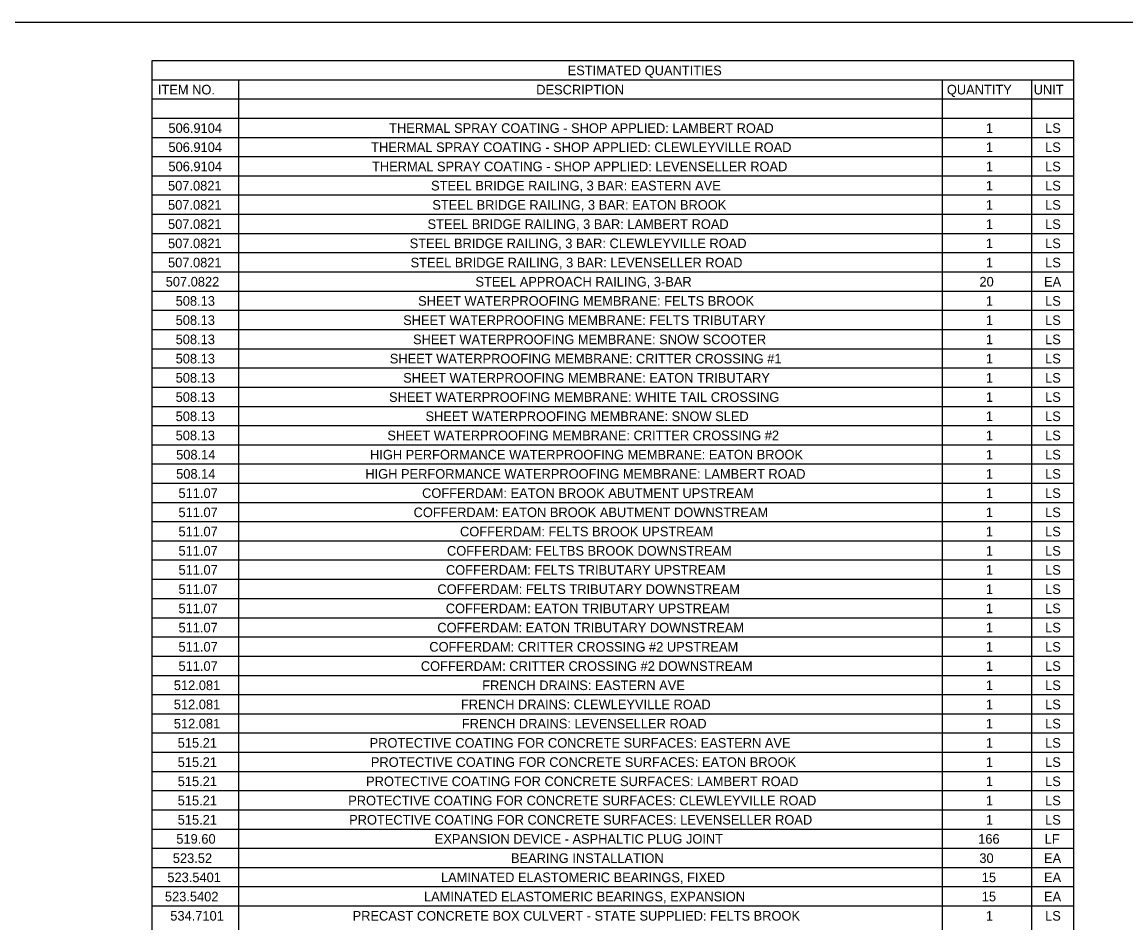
# Model space of a CAD drawing. Extents: x -18.7 to 5.6, y -2.7 to 4.
# Drawn here: x -16.637 to -15.505, y 3.091 to 4.014 of the extents above; entities that cross this region are included whole.
import ezdxf

# ---------------------------------------------------------------- set-up
doc = ezdxf.new("R2010")
doc.units = 0
doc.layers.add('ANNOTATION', color=7, linetype='Continuous')
doc.layers.add('BORDER', color=7, linetype='Continuous')

msp = doc.modelspace()

# ---------------------------------------------------------------- linework, layer by layer
at = {"layer": 'ANNOTATION'}
msp.add_lwpolyline([(-17.663, 4.0141), (-13.3075, 4.0141), (-13.3075, 2.1719), (-17.663, 2.1719)], close=True, dxfattribs=at)
at = {"layer": 'BORDER'}
for p, q in [((-16.5036, 3.9551), (-15.5593, 3.9551)), ((-16.415, 3.9551), (-16.415, 2.2424)), ((-15.6937, 3.9551), (-15.6937, 2.2424)), ((-15.6023, 3.9551), (-15.6023, 2.2424)), ((-16.5036, 3.9354), (-15.5593, 3.9354)), ((-16.5036, 3.9157), (-15.5593, 3.9157)), ((-16.5036, 3.896), (-15.5593, 3.896)), ((-16.5036, 3.8764), (-15.5593, 3.8764)), ((-16.5036, 3.8567), (-15.5593, 3.8567)), ((-16.5036, 3.837), (-15.5593, 3.837)), ((-16.5036, 3.8173), (-15.5593, 3.8173)), ((-16.5036, 3.7976), (-15.5593, 3.7976)), ((-16.5036, 3.7779), (-15.5593, 3.7779)), ((-16.5036, 3.7582), (-15.5593, 3.7582)), ((-16.5036, 3.7386), (-15.5593, 3.7386)), ((-16.5036, 3.7189), (-15.5593, 3.7189)), ((-16.5036, 3.6992), (-15.5593, 3.6992)), ((-16.5036, 3.6795), (-15.5593, 3.6795)), ((-16.5036, 3.6598), (-15.5593, 3.6598)), ((-16.5036, 3.6401), (-15.5593, 3.6401)), ((-16.5036, 3.6204), (-15.5593, 3.6204)), ((-16.5036, 3.6008), (-15.5593, 3.6008)), ((-16.5036, 3.5811), (-15.5593, 3.5811)), ((-16.5036, 3.5614), (-15.5593, 3.5614)), ((-16.5036, 3.5417), (-15.5593, 3.5417)), ((-16.5036, 3.522), (-15.5593, 3.522)), ((-16.5036, 3.5023), (-15.5593, 3.5023)), ((-16.5036, 3.4826), (-15.5593, 3.4826)), ((-16.5036, 3.463), (-15.5593, 3.463)), ((-16.5036, 3.4433), (-15.5593, 3.4433)), ((-16.5036, 3.4236), (-15.5593, 3.4236)), ((-16.5036, 3.4039), (-15.5593, 3.4039)), ((-16.5036, 3.3842), (-15.5593, 3.3842)), ((-16.5036, 3.3645), (-15.5593, 3.3645)), ((-16.5036, 3.3448), (-15.5593, 3.3448)), ((-16.5036, 3.3251), (-15.5593, 3.3251)), ((-16.5036, 3.3055), (-15.5593, 3.3055)), ((-16.5036, 3.2858), (-15.5593, 3.2858)), ((-16.5036, 3.2661), (-15.5593, 3.2661)), ((-16.5036, 3.2464), (-15.5593, 3.2464)), ((-16.5036, 3.2267), (-15.5593, 3.2267)), ((-16.5036, 3.207), (-15.5593, 3.207)), ((-16.5036, 3.1873), (-15.5593, 3.1873)), ((-16.5036, 3.1677), (-15.5593, 3.1677)), ((-16.5036, 3.148), (-15.5593, 3.148)), ((-16.5036, 3.1283), (-15.5593, 3.1283)), ((-16.5036, 3.1086), (-15.5593, 3.1086))]:
    msp.add_line(p, q, dxfattribs=at)
msp.add_lwpolyline([(-16.5036, 3.9748), (-15.5593, 3.9748), (-15.5593, 2.2424), (-16.5036, 2.2424)], close=True, dxfattribs=at)

# ---------------------------------------------------------------- texts
at = {"layer": 'ANNOTATION'}
for s, height, p in [('506.9104', 0.00984, (-16.4869, 3.9006)), ('THERMAL SPRAY COATING - SHOP APPLIED: LAMBERT ROAD', 0.009843, (-16.2607, 3.9006)), ('1', 0.00984, (-15.649, 3.9006)), ('LS', 0.00984, (-15.5883, 3.9006)), ('506.9104', 0.00984, (-16.4869, 3.881)), ('THERMAL SPRAY COATING - SHOP APPLIED: CLEWLEYVILLE ROAD', 0.009843, (-16.2791, 3.881)), ('1', 0.00984, (-15.649, 3.881)), ('LS', 0.00984, (-15.5883, 3.881)), ('506.9104', 0.00984, (-16.4869, 3.8613)), ('THERMAL SPRAY COATING - SHOP APPLIED: LEVENSELLER ROAD', 0.009843, (-16.2782, 3.8613)), ('1', 0.00984, (-15.649, 3.8613)), ('LS', 0.00984, (-15.5883, 3.8613)), ('507.0821', 0.00984, (-16.4873, 3.8416)), ('STEEL BRIDGE RAILING, 3 BAR: EASTERN AVE', 0.009843, (-16.2177, 3.8416)), ('1', 0.00984, (-15.649, 3.8416)), ('LS', 0.00984, (-15.5883, 3.8416)), ('507.0821', 0.00984, (-16.4873, 3.8219)), ('STEEL BRIDGE RAILING, 3 BAR: EATON BROOK', 0.009843, (-16.2164, 3.8219)), ('1', 0.00984, (-15.649, 3.8219)), ('LS', 0.00984, (-15.5883, 3.8219)), ('507.0821', 0.00984, (-16.4873, 3.8022)), ('STEEL BRIDGE RAILING, 3 BAR: LAMBERT ROAD', 0.009843, (-16.2213, 3.8022)), ('1', 0.00984, (-15.649, 3.8022)), ('LS', 0.00984, (-15.5883, 3.8022)), ('507.0821', 0.00984, (-16.4873, 3.7825)), ('STEEL BRIDGE RAILING, 3 BAR: CLEWLEYVILLE ROAD', 0.009843, (-16.2396, 3.7825)), ('1', 0.00984, (-15.649, 3.7825)), ('LS', 0.00984, (-15.5883, 3.7825)), ('507.0821', 0.00984, (-16.4873, 3.7628)), ('STEEL BRIDGE RAILING, 3 BAR: LEVENSELLER ROAD', 0.009843, (-16.2387, 3.7628)), ('1', 0.00984, (-15.649, 3.7628)), ('LS', 0.00984, (-15.5883, 3.7628)), ('507.0822', 0.00984, (-16.4897, 3.7432)), ('STEEL APPROACH RAILING, 3-BAR', 0.009843, (-16.1722, 3.7432)), ('20', 0.00984, (-15.6556, 3.7432)), ('EA', 0.00984, (-15.5894, 3.7432)), ('508.13', 0.00984, (-16.4795, 3.7235)), ('SHEET WATERPROOFING MEMBRANE: FELTS BROOK', 0.009843, (-16.231, 3.7235)), ('1', 0.00984, (-15.649, 3.7235)), ('LS', 0.00984, (-15.5883, 3.7235)), ('508.13', 0.00984, (-16.4795, 3.7038)), ('SHEET WATERPROOFING MEMBRANE: FELTS TRIBUTARY', 0.009843, (-16.2463, 3.7038)), ('1', 0.00984, (-15.649, 3.7038)), ('LS', 0.00984, (-15.5883, 3.7038)), ('508.13', 0.00984, (-16.4795, 3.6841)), ('SHEET WATERPROOFING MEMBRANE: SNOW SCOOTER', 0.009843, (-16.2362, 3.6841)), ('1', 0.00984, (-15.649, 3.6841)), ('LS', 0.00984, (-15.5883, 3.6841)), ('508.13', 0.00984, (-16.4795, 3.6644)), ('SHEET WATERPROOFING MEMBRANE: CRITTER CROSSING #1', 0.009843, (-16.26, 3.6644)), ('1', 0.00984, (-15.649, 3.6644)), ('LS', 0.00984, (-15.5883, 3.6644)), ('508.13', 0.00984, (-16.4795, 3.6447)), ('SHEET WATERPROOFING MEMBRANE: EATON TRIBUTARY', 0.009843, (-16.2463, 3.6447)), ('LS', 0.00984, (-15.5883, 3.6447)), ('1', 0.00984, (-15.649, 3.6447)), ('508.13', 0.00984, (-16.4795, 3.625)), ('SHEET WATERPROOFING MEMBRANE: WHITE TAIL CROSSING', 0.009843, (-16.2608, 3.625)), ('1', 0.00984, (-15.649, 3.625)), ('LS', 0.00984, (-15.5883, 3.625)), ('508.13', 0.00984, (-16.4795, 3.6053)), ('SHEET WATERPROOFING MEMBRANE: SNOW SLED', 0.009843, (-16.2234, 3.6053)), ('1', 0.00984, (-15.649, 3.6053)), ('LS', 0.00984, (-15.5883, 3.6053)), ('508.13', 0.00984, (-16.4795, 3.5857)), ('SHEET WATERPROOFING MEMBRANE: CRITTER CROSSING #2', 0.009843, (-16.2625, 3.5857)), ('1', 0.00984, (-15.649, 3.5857)), ('LS', 0.00984, (-15.5883, 3.5857)), ('508.14', 0.00984, (-16.479, 3.566)), ('HIGH PERFORMANCE WATERPROOFING MEMBRANE: EATON BROOK', 0.009843, (-16.2803, 3.566)), ('1', 0.00984, (-15.649, 3.566)), ('LS', 0.00984, (-15.5883, 3.566)), ('508.14', 0.00984, (-16.479, 3.5463)), ('HIGH PERFORMANCE WATERPROOFING MEMBRANE: LAMBERT ROAD', 0.009843, (-16.2851, 3.5463)), ('1', 0.00984, (-15.649, 3.5463)), ('LS', 0.00984, (-15.5883, 3.5463)), ('511.07', 0.00984, (-16.4766, 3.5266)), ('COFFERDAM: EATON BROOK ABUTMENT UPSTREAM', 0.009843, (-16.2269, 3.5266)), ('1', 0.00984, (-15.649, 3.5266)), ('LS', 0.00984, (-15.5883, 3.5266)), ('511.07', 0.00984, (-16.4766, 3.5069)), ('COFFERDAM: EATON BROOK ABUTMENT DOWNSTREAM', 0.009843, (-16.2356, 3.5069)), ('1', 0.00984, (-15.649, 3.5069)), ('LS', 0.00984, (-15.5883, 3.5069)), ('511.07', 0.00984, (-16.4766, 3.4872)), ('COFFERDAM: FELTS BROOK UPSTREAM', 0.009843, (-16.188, 3.4872)), ('1', 0.00984, (-15.649, 3.4872)), ('LS', 0.00984, (-15.5883, 3.4872)), ('511.07', 0.00984, (-16.4766, 3.4675)), ('COFFERDAM: FELTBS BROOK DOWNSTREAM', 0.009843, (-16.2014, 3.4675)), ('1', 0.00984, (-15.649, 3.4675)), ('LS', 0.00984, (-15.5883, 3.4675)), ('511.07', 0.00984, (-16.4766, 3.4479)), ('COFFERDAM: FELTS TRIBUTARY UPSTREAM', 0.009843, (-16.2025, 3.4479)), ('1', 0.00984, (-15.649, 3.4479)), ('LS', 0.00984, (-15.5883, 3.4479)), ('511.07', 0.00984, (-16.4766, 3.4282)), ('COFFERDAM: FELTS TRIBUTARY DOWNSTREAM', 0.009843, (-16.2112, 3.4282)), ('1', 0.00984, (-15.649, 3.4282)), ('LS', 0.00984, (-15.5883, 3.4282)), ('511.07', 0.00984, (-16.4766, 3.4085)), ('COFFERDAM: EATON TRIBUTARY UPSTREAM', 0.009843, (-16.2026, 3.4085)), ('1', 0.00984, (-15.649, 3.4085)), ('LS', 0.00984, (-15.5883, 3.4085)), ('511.07', 0.00984, (-16.4766, 3.3888)), ('COFFERDAM: EATON TRIBUTARY DOWNSTREAM', 0.009843, (-16.2113, 3.3888)), ('1', 0.00984, (-15.649, 3.3888)), ('LS', 0.00984, (-15.5883, 3.3888)), ('511.07', 0.00984, (-16.4766, 3.3691)), ('COFFERDAM: CRITTER CROSSING #2 UPSTREAM', 0.009843, (-16.2195, 3.3691)), ('1', 0.00984, (-15.649, 3.3691)), ('LS', 0.00984, (-15.5883, 3.3691)), ('511.07', 0.00984, (-16.4766, 3.3494)), ('COFFERDAM: CRITTER CROSSING #2 DOWNSTREAM', 0.009843, (-16.2282, 3.3494)), ('1', 0.00984, (-15.649, 3.3494)), ('LS', 0.00984, (-15.5883, 3.3494)), ('512.081', 0.00984, (-16.4814, 3.3297)), ('FRENCH DRAINS: EASTERN AVE', 0.009843, (-16.1653, 3.3297)), ('1', 0.00984, (-15.649, 3.3297)), ('LS', 0.00984, (-15.5883, 3.3297)), ('512.081', 0.00984, (-16.4814, 3.3101)), ('FRENCH DRAINS: CLEWLEYVILLE ROAD', 0.009843, (-16.1871, 3.3101)), ('1', 0.00984, (-15.649, 3.3101)), ('LS', 0.00984, (-15.5883, 3.3101)), ('512.081', 0.00984, (-16.4814, 3.2904)), ('FRENCH DRAINS: LEVENSELLER ROAD', 0.009843, (-16.1862, 3.2904)), ('1', 0.00984, (-15.649, 3.2904)), ('LS', 0.00984, (-15.5883, 3.2904)), ('515.21', 0.00984, (-16.4774, 3.2707)), ('PROTECTIVE COATING FOR CONCRETE SURFACES: EASTERN AVE', 0.009843, (-16.2807, 3.2707)), ('1', 0.00984, (-15.649, 3.2707)), ('LS', 0.00984, (-15.5883, 3.2707)), ('515.21', 0.00984, (-16.4774, 3.251)), ('PROTECTIVE COATING FOR CONCRETE SURFACES: EATON BROOK', 0.009843, (-16.2794, 3.251)), ('1', 0.00984, (-15.649, 3.251)), ('LS', 0.00984, (-15.5883, 3.251)), ('515.21', 0.00984, (-16.4774, 3.2313)), ('PROTECTIVE COATING FOR CONCRETE SURFACES: LAMBERT ROAD', 0.009843, (-16.2843, 3.2313)), ('1', 0.00984, (-15.649, 3.2313)), ('LS', 0.00984, (-15.5883, 3.2313)), ('515.21', 0.00984, (-16.4774, 3.2116)), ('PROTECTIVE COATING FOR CONCRETE SURFACES: CLEWLEYVILLE ROAD', 0.009843, (-16.3026, 3.2116)), ('1', 0.00984, (-15.649, 3.2116)), ('LS', 0.00984, (-15.5883, 3.2116)), ('515.21', 0.00984, (-16.4774, 3.1919)), ('PROTECTIVE COATING FOR CONCRETE SURFACES: LEVENSELLER ROAD', 0.009843, (-16.3017, 3.1919)), ('1', 0.00984, (-15.649, 3.1919)), ('LS', 0.00984, (-15.5883, 3.1919)), ('519.60', 0.00984, (-16.4788, 3.1723)), ('EXPANSION DEVICE - ASPHALTIC PLUG JOINT', 0.009843, (-16.2139, 3.1723)), ('166', 0.00984, (-15.6569, 3.1723)), ('LF', 0.00984, (-15.5887, 3.1723)), ('523.52', 0.00984, (-16.4824, 3.1526)), ('BEARING INSTALLATION', 0.009843, (-16.1358, 3.1526)), ('30', 0.00984, (-15.6557, 3.1526)), ('EA', 0.00984, (-15.5894, 3.1526)), ('523.5401', 0.00984, (-16.488, 3.1329)), ('LAMINATED ELASTOMERIC BEARINGS, FIXED', 0.009843, (-16.2076, 3.1329)), ('15', 0.00984, (-15.6532, 3.1329)), ('EA', 0.00984, (-15.5894, 3.1329)), ('523.5402', 0.00984, (-16.4905, 3.1132)), ('LAMINATED ELASTOMERIC BEARINGS, EXPANSION', 0.009843, (-16.225, 3.1132)), ('15', 0.00984, (-15.6532, 3.1132)), ('EA', 0.00984, (-15.5894, 3.1132)), ('534.7101', 0.00984, (-16.485, 3.0935)), ('PRECAST CONCRETE BOX CULVERT - STATE SUPPLIED: FELTS BROOK', 0.009843, (-16.2981, 3.0935)), ('1', 0.00984, (-15.649, 3.0935)), ('LS', 0.00984, (-15.5883, 3.0935))]:
    msp.add_text(s, height=height, dxfattribs=at).set_placement(p)
at = {"layer": 'BORDER'}
for s, height, p in [('ESTIMATED QUANTITIES', 0.009843, (-16.0777, 3.9597)), ('ITEM NO.', 0.00984, (-16.4977, 3.94)), ('DESCRIPTION', 0.009843, (-16.1099, 3.94)), ('QUANTITY', 0.00984, (-15.689, 3.94)), ('UNIT', 0.00984, (-15.6, 3.94))]:
    msp.add_text(s, height=height, dxfattribs=at).set_placement(p)

doc.saveas('drawing.dxf')
